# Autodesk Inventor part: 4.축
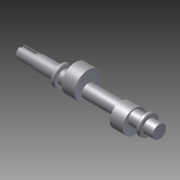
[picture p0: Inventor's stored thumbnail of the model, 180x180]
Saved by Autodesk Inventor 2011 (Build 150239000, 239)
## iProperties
Created: 2014-12
Part Number: 4.축
Document SubType Name: Modeling
Designer: user
Density: 1 g/cm^3
Author: user
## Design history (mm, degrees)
sketch "스케치1"
  geometry: L1 (90, 0)-(-90, 0); L2 (90, 0)-(90, 7.5); L3 (90, 7.5)-(66, 7.5); L4 (66, 7.5)-(66, 8.5); L5 (66, 8.5)-(39, 8.5); L6 (39, 8.5)-(39, 13); L7 (39, 13)-(34, 13); L8 (34, 13)-(34, 8.5); L9 (34, 8.5)-(-72, 8.5); L10 (-72, 8.5)-(-72, 13); L11 (-72, 13)-(-77, 13); L12 (-77, 13)-(-77, 8.5); L13 (-77, 8.5)-(-90, 8.5); L14 (-90, 8.5)-(-90, 0); 2 further points
  constraints: 28 end point, 8 parallel, 3 horizontal, 2 vertical, 1 coincident, 1 midpoint, 1 perpendicular
  dimensions: "d0" = 180 distance of L1.start L1.end; "d1" = 17 diameter of L13 L1; "d2" = 15 diameter of L3 L1; "d3" = 17 diameter of L5 L1; "d4" = 26 diameter of L7 L1; "d5" = 17 diameter of L9 L1; "d6" = 24 distance of L2.end L3.end; "d7" = 27 distance of L4.end L5.end; "d8" = 5 distance of L6.end L7.end; "d9" = 13 distance of L12.end L13.end; "d10" = 26 diameter of L11 L1; "d11" = 5 distance of L10.end L11.end
revolve "회전1" sketch "스케치1" stored, may be unused: angle "d12" = 90 deg
node "작업 평면1"
sketch "스케치2"
  geometry: C1 r 8.5 at (0, 0) reference; C2 r 15 at (5, 0); 1 further point
  constraints: 1 centre point, 1 horizontal alignment
  dimensions: "d14" = 30 diameter of C2; "d15" = 5 distance of C2.centre point (0, 0)
extrude "돌출1" join sketch "스케치2" distance "d16" = 17; taper "d17" = 0 deg
node "작업 평면2"
sketch "스케치3"
  geometry: C1 r 8.5 at (0, 5) reference; C2 r 17.5 at (0, 11); 1 further point
  constraints: 1 centre point, 1 vertical alignment
  dimensions: "d19" = 35 diameter of C2; "d20" = 6 distance of point (0, 5) C2.centre
extrude "돌출2" join sketch "스케치3" distance "d21" = 17; taper "d22" = 0 deg
node "작업 평면3"
sketch "스케치4" dims "d23" = 5
  geometry: L1 (168, 4)-(168, -4) reference; L2 (168, -4)-(155, -4) reference; L3 (155, -4)-(155, -10.618) reference; L4 (155, -10.618)-(150, -10.618) reference; L5 (150, -10.618)-(150, -4) reference; L6 (150, -4)-(135.5, -4) reference; L7 (135.5, -4)-(135.5, -8.292) reference; L8 (135.5, -8.292)-(118.5, -8.292) reference; L9 (118.5, -8.292)-(118.5, -4) reference; L10 (118.5, -4)-(75.5, -4) reference; L11 (75.5, -4)-(75.5, -17.436) reference; L12 (75.5, -17.436)-(58.5, -17.436) reference; L13 (58.5, -17.436)-(58.5, -4) reference; L14 (58.5, -4)-(44, -4) reference; L15 (44, -4)-(44, -10.618) reference; L16 (44, -10.618)-(39, -10.618) reference; L17 (39, -10.618)-(39, -4) reference; L18 (39, -4)-(12, -4) reference; L19 (12, -4)-(12, 0) reference; L20 (12, 0)-(12, 4) reference; L21 (12, 4)-(39, 4) reference; L22 (39, 4)-(39, 10.618) reference; L23 (39, 10.618)-(44, 10.618) reference; L24 (44, 10.618)-(44, 4) reference; L25 (44, 4)-(58.5, 4) reference; L26 (58.5, 4)-(58.5, 17.436) reference; L27 (58.5, 17.436)-(75.5, 17.436) reference; L28 (75.5, 17.436)-(75.5, 4) reference; L29 (75.5, 4)-(118.5, 4) reference; L30 (118.5, 4)-(118.5, 8.292) reference; L31 (118.5, 8.292)-(135.5, 8.292) reference; L32 (135.5, 8.292)-(135.5, 4) reference; L33 (135.5, 4)-(150, 4) reference; L34 (150, 4)-(150, 10.618) reference; L35 (150, 10.618)-(155, 10.618) reference; L36 (155, 10.618)-(155, 4) reference; L37 (155, 4)-(168, 4) reference; L38 (12, 0)-(-12, 0) reference; L39 (5.5, 2.5)-(-16.864, 2.5); L40 (-16.864, 2.5)-(-16.864, -2.5); L41 (-16.864, -2.5)-(5.5, -2.5); L42 (5.5, -2.5)-(5.5, 2.5); L43 (-12, 7.5)-(-12, -7.5) reference; 2 further points
  constraints: 8 end point, 2 parallel, 1 horizontal, 1 perpendicular, 1 point on line, 1 vertical alignment, 2 other
  dimensions: "d24" = 5 distance of L39.end L40.end; "d25" = 20 dimension on L43
extrude "돌출3" cut sketch "스케치4" distance "d26" = 3; taper "d27" = 0 deg
chamfer "모따기1" distance "d28" = 1; stored, may be unused: second distance "d29" = 2, angle "d30" = 45 deg
node "솔리드1"
node "절단 모서리 투영1"
node "절단 모서리 투영2"
node "절단 모서리 투영3"
other parameters: "d13" = -32.5, "d18" = 43
